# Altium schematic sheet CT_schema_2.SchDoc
size 289 x 230 mm
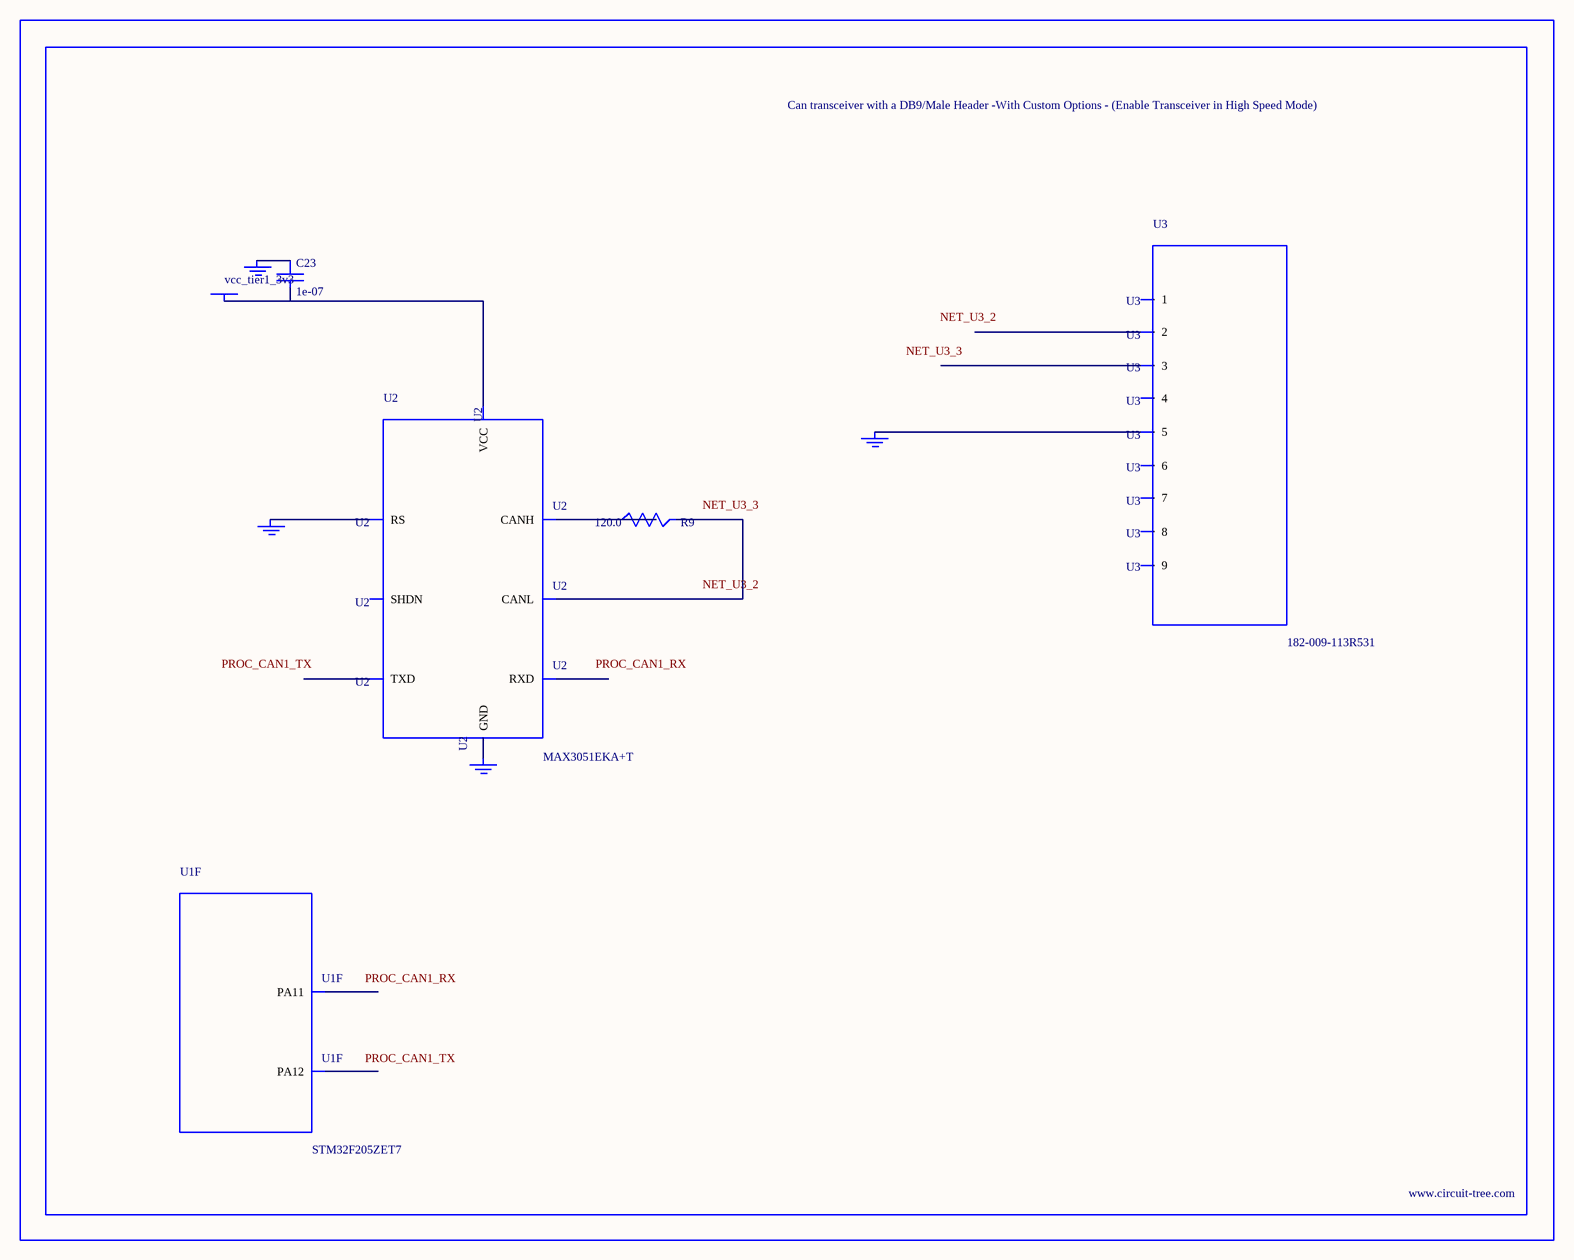
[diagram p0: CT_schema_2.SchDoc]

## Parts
BORDER1  (no value)
C23  1e-07  [C0402]
GND_INSTANCE_1_0  (no value)
GND_INSTANCE_1_1  (no value)
GND_INSTANCE_1_2  (no value)
GND_INSTANCE_1_3  (no value)
POWER_INSTANCE_1_0  vcc_tier1_3v3
R9  120.0  [R0603]
U1  STM32F205ZET7  [LQFP144]  (part F of 13)
U2  MAX3051EKA+T  [SOT-23-8]
U3  182-009-113R531  [182-009-MALE]

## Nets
NetC23_1: C23.1 GND_INSTANCE_1_0.0(GND)
NetC23_2: C23.2 POWER_INSTANCE_1_0.0(PWR) U2.3(VCC)
NetGND_INSTANCE_1_1_0: GND_INSTANCE_1_1.0(GND) U2.8(RS)
NetGND_INSTANCE_1_2_0: GND_INSTANCE_1_2.0(GND) U2.2(GND)
NetGND_INSTANCE_1_3_0: GND_INSTANCE_1_3.0(GND) U3.5
NetR9_1: R9.1 U2.7(CANH)
NetR9_2: R9.2 U2.6(CANL)

Not connected (* = marked no-connect by the designer): U1 103(PA11) 104(PA12); U2 1(TXD) 4(RXD) 5(SHDN); U3 1 2 3 4 6 7 8 9

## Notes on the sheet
- Labels drawn without touching a wire or pin: NET_U3_2, NET_U3_3, PROC_CAN1_RX, PROC_CAN1_TX

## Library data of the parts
BORDER1 = BORDER_PAGE1
C23 = C0402C104K3RACTU
GND_INSTANCE_1_0-GND_INSTANCE_1_3 = GND
POWER_INSTANCE_1_0 = PWR
R9 = RC0603JR-07120RL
